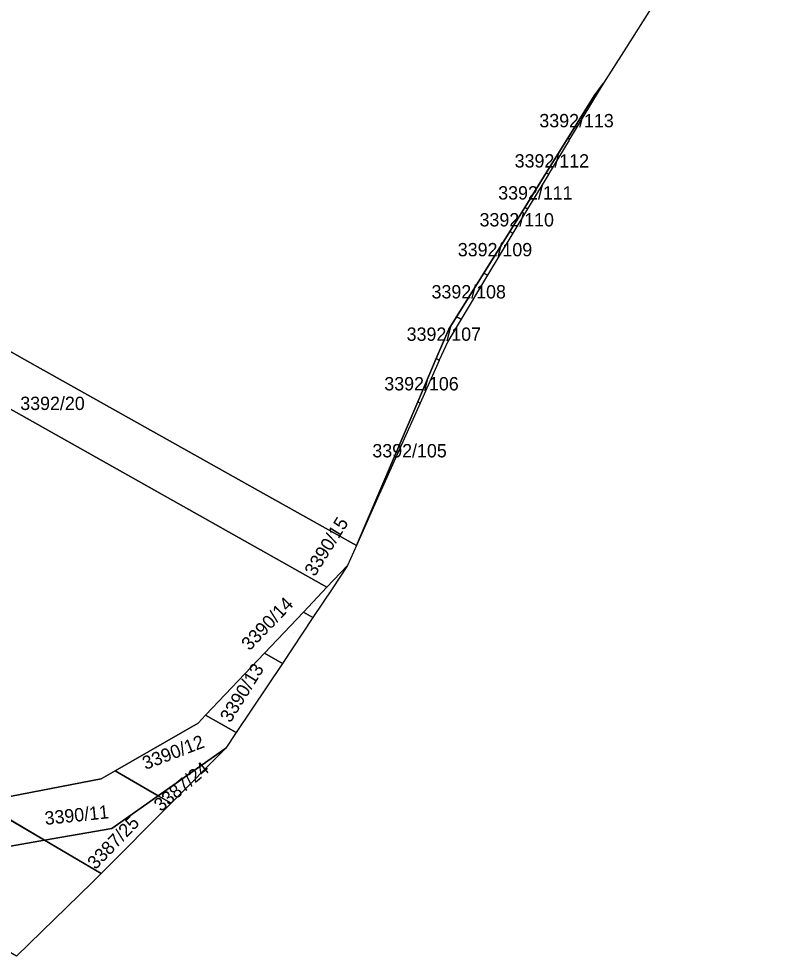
# Model space of a CAD drawing. Extents: x -262715 to -259381, y -1237238 to -1231182.
# Drawn here: x -261530.6 to -261416.5, y -1236783.3 to -1236642.6 of the extents above; entities that cross this region are included whole.
import ezdxf

# ---------------------------------------------------------------- set-up
doc = ezdxf.new("R2010")
doc.units = 0
for name, color, linetype in [('body_kn', 7, 'Continuous'), ('katuz_linie', 7, 'Continuous'), ('kladpar_druhypozemkov', 7, 'Continuous'), ('kladpar_hranice', 7, 'Continuous'), ('kladpar_parcelnecisla', 7, 'Continuous'), ('kladpar_plochy', 7, 'Continuous'), ('kladpar_sipky', 7, 'Continuous'), ('zuob_linie', 7, 'Continuous'), ('zuob_plochy', 7, 'Continuous')]:
    doc.layers.add(name, color=color, linetype=linetype)

msp = doc.modelspace()

# ---------------------------------------------------------------- linework, layer by layer
at = {"layer": 'body_kn'}
for p, q in [((-261439.9, -1236647.54), (-261439.9, -1236647.54)), ((-261442.9, -1236652.28), (-261442.9, -1236652.28)), ((-261444.29, -1236654.17), (-261444.29, -1236654.17)), ((-261443.68, -1236653.57), (-261443.68, -1236653.57)), ((-261448.25, -1236660.53), (-261448.25, -1236660.53)), ((-261448.25, -1236660.53), (-261448.25, -1236660.53)), ((-261448.03, -1236660.79), (-261448.03, -1236660.79)), ((-261447.97, -1236660.68), (-261447.97, -1236660.68)), ((-261447.97, -1236660.68), (-261447.97, -1236660.68)), ((-261451.48, -1236665.72), (-261451.48, -1236665.72)), ((-261451.48, -1236665.72), (-261451.48, -1236665.72)), ((-261451.15, -1236665.97), (-261451.15, -1236665.97)), ((-261451.12, -1236665.91), (-261451.12, -1236665.91)), ((-261451.12, -1236665.91), (-261451.12, -1236665.91)), ((-261454.71, -1236670.9), (-261454.71, -1236670.9)), ((-261454.71, -1236670.9), (-261454.71, -1236670.9)), ((-261454.27, -1236671.14), (-261454.27, -1236671.14)), ((-261454.27, -1236671.14), (-261454.27, -1236671.14)), ((-261456.96, -1236674.52), (-261456.96, -1236674.52)), ((-261456.96, -1236674.52), (-261456.96, -1236674.52)), ((-261456.47, -1236674.79), (-261456.47, -1236674.79)), ((-261456.47, -1236674.79), (-261456.47, -1236674.79)), ((-261460.85, -1236680.77), (-261460.85, -1236680.77)), ((-261460.85, -1236680.77), (-261460.85, -1236680.77)), ((-261460.27, -1236681.09), (-261460.27, -1236681.09)), ((-261460.27, -1236681.09), (-261460.27, -1236681.09)), ((-261464.93, -1236687.32), (-261464.93, -1236687.32)), ((-261464.93, -1236687.32), (-261464.93, -1236687.32)), ((-261464.25, -1236687.69), (-261464.25, -1236687.69)), ((-261464.25, -1236687.69), (-261464.25, -1236687.69)), ((-261466.08, -1236689.17), (-261466.08, -1236689.17)), ((-261466.25, -1236691.01), (-261466.25, -1236691.01)), ((-261467.97, -1236693.59), (-261467.97, -1236693.59)), ((-261467.97, -1236693.59), (-261467.97, -1236693.59)), ((-261467.52, -1236693.86), (-261467.52, -1236693.86)), ((-261467.51, -1236693.84), (-261467.51, -1236693.84)), ((-261467.51, -1236693.84), (-261467.51, -1236693.84)), ((-261528.1, -1236694.63), (-261528.1, -1236694.63)), ((-261470.74, -1236700.09), (-261470.74, -1236700.09)), ((-261470.74, -1236700.09), (-261470.74, -1236700.09)), ((-261470.4, -1236700.28), (-261470.4, -1236700.28)), ((-261470.4, -1236700.28), (-261470.4, -1236700.28)), ((-261515.83, -1236710.16), (-261515.83, -1236710.16)), ((-261495.14, -1236713.11), (-261495.14, -1236713.11)), ((-261476.47, -1236713.87), (-261476.47, -1236713.87)), ((-261476.57, -1236714.09), (-261476.57, -1236714.09)), ((-261479.94, -1236721.62), (-261479.94, -1236721.62)), ((-261479.94, -1236721.62), (-261479.94, -1236721.62)), ((-261481.29, -1236724.65), (-261481.29, -1236724.65)), ((-261484.37, -1236727.9), (-261484.37, -1236727.9)), ((-261484.37, -1236727.9), (-261484.37, -1236727.9)), ((-261483.6, -1236728.13), (-261483.6, -1236728.13)), ((-261487.9, -1236731.62), (-261487.9, -1236731.62)), ((-261487.9, -1236731.62), (-261487.9, -1236731.62)), ((-261486.46, -1236732.42), (-261486.46, -1236732.42)), ((-261486.46, -1236732.42), (-261486.46, -1236732.42)), ((-261493.75, -1236737.79), (-261493.75, -1236737.79)), ((-261493.75, -1236737.79), (-261493.75, -1236737.79)), ((-261491.05, -1236739.32), (-261491.05, -1236739.32)), ((-261491.05, -1236739.32), (-261491.05, -1236739.32)), ((-261502.57, -1236747.11), (-261502.57, -1236747.11)), ((-261502.57, -1236747.11), (-261502.57, -1236747.11)), ((-261503.69, -1236748.29), (-261503.69, -1236748.29)), ((-261497.96, -1236749.7), (-261497.96, -1236749.7)), ((-261497.96, -1236749.7), (-261497.96, -1236749.7)), ((-261499.52, -1236752.05), (-261499.52, -1236752.05)), ((-261516.11, -1236755.43), (-261516.11, -1236755.43)), ((-261516.11, -1236755.43), (-261516.11, -1236755.43)), ((-261518.22, -1236756.65), (-261518.22, -1236756.65)), ((-261509.65, -1236759.19), (-261509.65, -1236759.19)), ((-261509.65, -1236759.19), (-261509.65, -1236759.19)), ((-261507.73, -1236760.3), (-261507.73, -1236760.3)), ((-261507.73, -1236760.3), (-261507.73, -1236760.3)), ((-261516.6, -1236764.09), (-261516.6, -1236764.09)), ((-261526.69, -1236765.86), (-261526.69, -1236765.86)), ((-261526.69, -1236765.86), (-261526.69, -1236765.86)), ((-261518.23, -1236770.84), (-261518.23, -1236770.84)), ((-261518.23, -1236770.84), (-261518.23, -1236770.84)), ((-261519.57, -1236772.19), (-261519.57, -1236772.19))]:
    msp.add_line(p, q, dxfattribs=at)
at = {"layer": 'katuz_linie'}
msp.add_lwpolyline([(-261423.28, -1236621.31), (-261439.9, -1236647.54), (-261442.9, -1236652.28), (-261443.68, -1236653.57), (-261447.97, -1236660.68), (-261448.03, -1236660.79), (-261451.12, -1236665.91), (-261451.15, -1236665.97), (-261454.27, -1236671.14), (-261456.47, -1236674.79), (-261460.27, -1236681.09), (-261464.25, -1236687.69), (-261466.25, -1236691.01), (-261467.51, -1236693.84), (-261467.52, -1236693.86), (-261470.4, -1236700.28), (-261476.47, -1236713.87), (-261476.57, -1236714.09), (-261479.94, -1236721.62), (-261481.29, -1236724.65), (-261483.6, -1236728.13), (-261486.46, -1236732.42), (-261491.05, -1236739.32), (-261497.96, -1236749.7), (-261499.52, -1236752.05), (-261507.73, -1236760.3), (-261518.23, -1236770.84), (-261519.57, -1236772.19), (-261530.9, -1236783.26)], dxfattribs=at)
at = {"layer": 'kladpar_druhypozemkov'}
for p, q in [((-261446.4, -1236657.83), (-261446.4, -1236657.83)), ((-261450.05, -1236663.73), (-261450.05, -1236663.73)), ((-261452.82, -1236668.35), (-261452.82, -1236668.35)), ((-261455.31, -1236672.41), (-261455.31, -1236672.41)), ((-261457.99, -1236676.77), (-261457.99, -1236676.77)), ((-261461.79, -1236683.11), (-261461.79, -1236683.11)), ((-261465.48, -1236688.95), (-261465.48, -1236688.95)), ((-261469.01, -1236696.61), (-261469.01, -1236696.61)), ((-261525.16, -1236699.5), (-261525.16, -1236699.5)), ((-261471.8, -1236703.11), (-261471.8, -1236703.11)), ((-261486.85, -1236731.4), (-261486.85, -1236731.4)), ((-261491.01, -1236737.59), (-261491.01, -1236737.59)), ((-261500.27, -1236747.1), (-261500.27, -1236747.1)), ((-261505.42, -1236751.62), (-261505.42, -1236751.62)), ((-261507.92, -1236758.51), (-261507.92, -1236758.51)), ((-261521.72, -1236761.24), (-261521.72, -1236761.24)), ((-261519.87, -1236767.42), (-261519.87, -1236767.42))]:
    msp.add_line(p, q, dxfattribs=at)
at = {"layer": 'kladpar_hranice'}
for p, q in [((-261451.48, -1236665.72), (-261448.25, -1236660.53)), ((-261448.25, -1236660.53), (-261447.97, -1236660.68)), ((-261447.97, -1236660.68), (-261448.25, -1236660.53)), ((-261454.71, -1236670.9), (-261451.48, -1236665.72)), ((-261451.12, -1236665.91), (-261451.48, -1236665.72)), ((-261451.48, -1236665.72), (-261451.12, -1236665.91)), ((-261456.96, -1236674.52), (-261454.71, -1236670.9)), ((-261454.27, -1236671.14), (-261456.47, -1236674.79)), ((-261454.27, -1236671.14), (-261454.71, -1236670.9)), ((-261454.71, -1236670.9), (-261454.27, -1236671.14)), ((-261460.85, -1236680.77), (-261456.96, -1236674.52)), ((-261456.96, -1236674.52), (-261456.47, -1236674.79)), ((-261456.47, -1236674.79), (-261456.96, -1236674.52)), ((-261456.47, -1236674.79), (-261460.27, -1236681.09)), ((-261464.93, -1236687.32), (-261460.85, -1236680.77)), ((-261460.27, -1236681.09), (-261464.25, -1236687.69)), ((-261460.85, -1236680.77), (-261460.27, -1236681.09)), ((-261460.27, -1236681.09), (-261460.85, -1236680.77)), ((-261464.93, -1236687.32), (-261464.25, -1236687.69)), ((-261464.25, -1236687.69), (-261464.93, -1236687.32)), ((-261470.74, -1236700.09), (-261467.97, -1236693.59)), ((-261467.97, -1236693.59), (-261467.51, -1236693.84)), ((-261467.51, -1236693.84), (-261467.97, -1236693.59)), ((-261479.94, -1236721.62), (-261470.74, -1236700.09)), ((-261470.74, -1236700.09), (-261470.4, -1236700.28)), ((-261470.4, -1236700.28), (-261470.74, -1236700.09)), ((-261493.75, -1236737.79), (-261487.9, -1236731.62)), ((-261486.46, -1236732.42), (-261487.9, -1236731.62)), ((-261487.9, -1236731.62), (-261486.46, -1236732.42)), ((-261486.46, -1236732.42), (-261491.05, -1236739.32)), ((-261502.57, -1236747.11), (-261493.75, -1236737.79)), ((-261491.05, -1236739.32), (-261493.75, -1236737.79)), ((-261493.75, -1236737.79), (-261491.05, -1236739.32)), ((-261491.05, -1236739.32), (-261497.96, -1236749.7)), ((-261502.57, -1236747.11), (-261497.96, -1236749.7)), ((-261497.96, -1236749.7), (-261502.57, -1236747.11)), ((-261509.65, -1236759.19), (-261516.11, -1236755.43)), ((-261516.11, -1236755.43), (-261509.65, -1236759.19)), ((-261526.69, -1236765.86), (-261536.36, -1236760.16)), ((-261536.36, -1236760.16), (-261526.69, -1236765.86)), ((-261507.73, -1236760.3), (-261518.23, -1236770.84)), ((-261507.73, -1236760.3), (-261509.65, -1236759.19)), ((-261509.65, -1236759.19), (-261507.73, -1236760.3)), ((-261518.23, -1236770.84), (-261526.69, -1236765.86)), ((-261526.69, -1236765.86), (-261518.23, -1236770.84))]:
    msp.add_line(p, q, dxfattribs=at)
for points in [[(-261581.96, -1236557.12), (-261580.91, -1236548.23), (-261580.99, -1236545.13), (-261581.51, -1236525.81), (-261553.39, -1236545.48), (-261539.01, -1236515.59), (-261475.98, -1236549.48), (-261416.54, -1236607.89), (-261423.28, -1236621.31), (-261439.9, -1236647.54), (-261442.9, -1236652.28), (-261444.29, -1236654.17), (-261448.25, -1236660.53), (-261451.48, -1236665.72), (-261454.71, -1236670.9), (-261456.96, -1236674.52)], [(-261448.25, -1236660.53), (-261444.29, -1236654.17), (-261442.9, -1236652.28), (-261443.68, -1236653.57), (-261447.97, -1236660.68)], [(-261479.94, -1236721.62), (-261481.29, -1236724.65), (-261484.37, -1236727.9), (-261515.83, -1236710.16), (-261530.91, -1236701.65), (-261570.28, -1236679.67), (-261587.66, -1236669.96), (-261587.44, -1236661.56), (-261562.16, -1236675.49), (-261528.1, -1236694.63), (-261495.14, -1236713.11), (-261479.94, -1236721.62)], [(-261447.97, -1236660.68), (-261448.03, -1236660.79), (-261451.12, -1236665.91)], [(-261451.12, -1236665.91), (-261451.15, -1236665.97), (-261454.27, -1236671.14)], [(-261588.03, -1236684.42), (-261587.66, -1236669.96), (-261570.28, -1236679.67), (-261530.91, -1236701.65), (-261515.83, -1236710.16), (-261484.37, -1236727.9)], [(-261456.96, -1236674.52), (-261460.85, -1236680.77), (-261464.93, -1236687.32), (-261466.08, -1236689.17), (-261467.97, -1236693.59), (-261470.74, -1236700.09), (-261479.94, -1236721.62), (-261495.14, -1236713.11), (-261528.1, -1236694.63), (-261562.16, -1236675.49)], [(-261467.97, -1236693.59), (-261466.08, -1236689.17), (-261464.93, -1236687.32)], [(-261464.25, -1236687.69), (-261466.25, -1236691.01), (-261467.51, -1236693.84)], [(-261467.51, -1236693.84), (-261467.52, -1236693.86), (-261470.4, -1236700.28)], [(-261484.37, -1236727.9), (-261487.9, -1236731.62), (-261493.75, -1236737.79), (-261502.57, -1236747.11), (-261503.69, -1236748.29), (-261516.11, -1236755.43), (-261518.22, -1236756.65), (-261536.36, -1236760.16), (-261537.81, -1236760.44), (-261554.67, -1236756.97), (-261574.56, -1236742.18), (-261578.19, -1236735.52), (-261585.14, -1236722.79), (-261586.26, -1236714.69), (-261587.48, -1236705.78), (-261587.78, -1236703.62), (-261587.85, -1236699.27)], [(-261470.4, -1236700.28), (-261476.47, -1236713.87), (-261476.57, -1236714.09), (-261479.94, -1236721.62)], [(-261487.9, -1236731.62), (-261484.37, -1236727.9), (-261481.29, -1236724.65), (-261483.6, -1236728.13), (-261486.46, -1236732.42)], [(-261526.69, -1236765.86), (-261538.34, -1236767.9), (-261558.51, -1236763.51), (-261571.43, -1236755.44), (-261580.74, -1236746.42), (-261585.18, -1236739.92), (-261590, -1236730.13), (-261585.13, -1236751.39)], [(-261585.13, -1236751.39), (-261590, -1236730.13), (-261585.18, -1236739.92), (-261580.74, -1236746.42), (-261571.43, -1236755.44), (-261558.51, -1236763.51), (-261538.34, -1236767.9), (-261526.69, -1236765.86)], [(-261516.11, -1236755.43), (-261503.69, -1236748.29), (-261502.57, -1236747.11)], [(-261497.96, -1236749.7), (-261499.52, -1236752.05), (-261509.65, -1236759.19)], [(-261509.65, -1236759.19), (-261499.52, -1236752.05), (-261507.73, -1236760.3)], [(-261536.36, -1236760.16), (-261518.22, -1236756.65), (-261516.11, -1236755.43)], [(-261509.65, -1236759.19), (-261516.6, -1236764.09), (-261526.69, -1236765.86)], [(-261526.69, -1236765.86), (-261516.6, -1236764.09), (-261509.65, -1236759.19)], [(-261518.23, -1236770.84), (-261519.57, -1236772.19), (-261530.9, -1236783.26)]]:
    msp.add_lwpolyline(points, dxfattribs=at)
at = {"layer": 'kladpar_plochy'}
msp.add_lwpolyline([(-261423.28, -1236621.31), (-261439.9, -1236647.54), (-261442.9, -1236652.28), (-261444.29, -1236654.17), (-261448.25, -1236660.53), (-261451.48, -1236665.72), (-261454.71, -1236670.9), (-261456.96, -1236674.52), (-261460.85, -1236680.77), (-261464.93, -1236687.32), (-261466.08, -1236689.17), (-261467.97, -1236693.59), (-261470.74, -1236700.09), (-261479.94, -1236721.62), (-261495.14, -1236713.11), (-261528.1, -1236694.63), (-261562.16, -1236675.49), (-261558.33, -1236668.58), (-261587.21, -1236652.61), (-261586.6, -1236629.3)], dxfattribs=at)
for points in [[(-261448.25, -1236660.53), (-261444.29, -1236654.17), (-261442.9, -1236652.28), (-261443.68, -1236653.57), (-261447.97, -1236660.68)], [(-261451.48, -1236665.72), (-261448.25, -1236660.53), (-261447.97, -1236660.68), (-261448.03, -1236660.79), (-261451.12, -1236665.91)], [(-261479.94, -1236721.62), (-261481.29, -1236724.65), (-261484.37, -1236727.9), (-261515.83, -1236710.16), (-261530.91, -1236701.65), (-261570.28, -1236679.67), (-261587.66, -1236669.96), (-261587.44, -1236661.56), (-261562.16, -1236675.49), (-261528.1, -1236694.63), (-261495.14, -1236713.11)], [(-261454.27, -1236671.14), (-261454.71, -1236670.9), (-261451.48, -1236665.72), (-261451.12, -1236665.91), (-261451.15, -1236665.97)], [(-261484.37, -1236727.9), (-261487.9, -1236731.62), (-261493.75, -1236737.79), (-261502.57, -1236747.11), (-261503.69, -1236748.29), (-261516.11, -1236755.43), (-261518.22, -1236756.65), (-261536.36, -1236760.16), (-261537.81, -1236760.44), (-261554.67, -1236756.97), (-261574.56, -1236742.18), (-261578.19, -1236735.52), (-261585.14, -1236722.79), (-261586.26, -1236714.69), (-261587.48, -1236705.78), (-261587.78, -1236703.62), (-261587.85, -1236699.27), (-261578.96, -1236704.26), (-261576.72, -1236690.83), (-261588.03, -1236684.42), (-261587.66, -1236669.96), (-261570.28, -1236679.67), (-261530.91, -1236701.65), (-261515.83, -1236710.16)], [(-261454.71, -1236670.9), (-261454.27, -1236671.14), (-261456.47, -1236674.79), (-261456.96, -1236674.52)], [(-261460.85, -1236680.77), (-261456.96, -1236674.52), (-261456.47, -1236674.79), (-261460.27, -1236681.09)], [(-261464.93, -1236687.32), (-261460.85, -1236680.77), (-261460.27, -1236681.09), (-261464.25, -1236687.69)], [(-261467.97, -1236693.59), (-261466.08, -1236689.17), (-261464.93, -1236687.32), (-261464.25, -1236687.69), (-261466.25, -1236691.01), (-261467.51, -1236693.84)], [(-261470.74, -1236700.09), (-261467.97, -1236693.59), (-261467.51, -1236693.84), (-261467.52, -1236693.86), (-261470.4, -1236700.28)], [(-261479.94, -1236721.62), (-261470.74, -1236700.09), (-261470.4, -1236700.28), (-261476.47, -1236713.87), (-261476.57, -1236714.09)], [(-261536.36, -1236760.16), (-261526.69, -1236765.86), (-261538.34, -1236767.9), (-261558.51, -1236763.51), (-261571.43, -1236755.44), (-261580.74, -1236746.42), (-261585.18, -1236739.92), (-261590, -1236730.13), (-261585.13, -1236751.39), (-261595.45, -1236745.32), (-261597.63, -1236735.85), (-261599.71, -1236726.01), (-261600.23, -1236722.54), (-261578.19, -1236735.52), (-261574.56, -1236742.18), (-261554.67, -1236756.97), (-261537.81, -1236760.44)], [(-261487.9, -1236731.62), (-261484.37, -1236727.9), (-261481.29, -1236724.65), (-261483.6, -1236728.13), (-261486.46, -1236732.42)], [(-261526.69, -1236765.86), (-261518.23, -1236770.84), (-261519.57, -1236772.19), (-261530.9, -1236783.26), (-261585.13, -1236751.39), (-261590, -1236730.13), (-261585.18, -1236739.92), (-261580.74, -1236746.42), (-261571.43, -1236755.44), (-261558.51, -1236763.51), (-261538.34, -1236767.9)], [(-261487.9, -1236731.62), (-261486.46, -1236732.42), (-261491.05, -1236739.32), (-261493.75, -1236737.79)], [(-261493.75, -1236737.79), (-261491.05, -1236739.32), (-261497.96, -1236749.7), (-261502.57, -1236747.11)], [(-261502.57, -1236747.11), (-261497.96, -1236749.7), (-261499.52, -1236752.05), (-261509.65, -1236759.19), (-261516.11, -1236755.43), (-261503.69, -1236748.29)], [(-261509.65, -1236759.19), (-261499.52, -1236752.05), (-261507.73, -1236760.3)], [(-261516.11, -1236755.43), (-261509.65, -1236759.19), (-261516.6, -1236764.09), (-261526.69, -1236765.86), (-261536.36, -1236760.16), (-261518.22, -1236756.65)], [(-261509.65, -1236759.19), (-261507.73, -1236760.3), (-261518.23, -1236770.84), (-261526.69, -1236765.86), (-261516.6, -1236764.09)]]:
    msp.add_lwpolyline(points, close=True, dxfattribs=at)
at = {"layer": 'kladpar_sipky'}
for p, q in [((-261486.14, -1236730.28), (-261486.14, -1236730.28)), ((-261489.42, -1236734.72), (-261489.42, -1236734.72))]:
    msp.add_line(p, q, dxfattribs=at)
at = {"layer": 'zuob_linie'}
msp.add_lwpolyline([(-261423.28, -1236621.31), (-261439.9, -1236647.54), (-261442.9, -1236652.28), (-261443.68, -1236653.57), (-261447.97, -1236660.68), (-261448.03, -1236660.79), (-261451.12, -1236665.91), (-261451.15, -1236665.97), (-261454.27, -1236671.14), (-261456.47, -1236674.79), (-261460.27, -1236681.09), (-261464.25, -1236687.69), (-261466.25, -1236691.01), (-261467.51, -1236693.84), (-261467.52, -1236693.86), (-261470.4, -1236700.28), (-261476.47, -1236713.87), (-261476.57, -1236714.09), (-261479.94, -1236721.62), (-261481.29, -1236724.65), (-261483.6, -1236728.13), (-261486.46, -1236732.42), (-261491.05, -1236739.32), (-261497.96, -1236749.7), (-261499.52, -1236752.05), (-261507.73, -1236760.3), (-261518.23, -1236770.84), (-261519.57, -1236772.19), (-261530.9, -1236783.26)], dxfattribs=at)
at = {"layer": 'zuob_plochy'}
msp.add_lwpolyline([(-261423.28, -1236621.31), (-261439.9, -1236647.54), (-261442.9, -1236652.28), (-261443.68, -1236653.57), (-261447.97, -1236660.68), (-261448.03, -1236660.79), (-261451.12, -1236665.91), (-261451.15, -1236665.97), (-261454.27, -1236671.14), (-261456.47, -1236674.79), (-261460.27, -1236681.09), (-261464.25, -1236687.69), (-261466.25, -1236691.01), (-261467.51, -1236693.84), (-261467.52, -1236693.86), (-261470.4, -1236700.28), (-261476.47, -1236713.87), (-261476.57, -1236714.09), (-261479.94, -1236721.62), (-261481.29, -1236724.65), (-261483.6, -1236728.13), (-261486.46, -1236732.42), (-261491.05, -1236739.32), (-261497.96, -1236749.7), (-261499.52, -1236752.05), (-261507.73, -1236760.3), (-261518.23, -1236770.84), (-261519.57, -1236772.19), (-261530.9, -1236783.26)], dxfattribs=at)

# ---------------------------------------------------------------- texts
at = {"layer": 'kladpar_parcelnecisla'}
for s, p in [('3392/113', (-261452.51, -1236658.88)), ('3392/112', (-261456.21, -1236664.92)), ('3392/111', (-261458.68, -1236669.72)), ('3392/110', (-261461.48, -1236673.76)), ('3392/109', (-261464.74, -1236678.24)), ('3392/108', (-261468.68, -1236684.56)), ('3392/107', (-261472.41, -1236690.92)), ('3392/106', (-261475.76, -1236698.36)), ('3392/20', (-261530.35, -1236701.3)), ('3392/105', (-261477.55, -1236708.41))]:
    msp.add_text(s, height=2, dxfattribs=at).set_placement(p)
for s, rotation, p in [('3390/15', 58, (-261486.18, -1236726.4)), ('3390/14', 46, (-261495.97, -1236737.52)), ('3390/13', 58, (-261498.85, -1236748.34)), ('3390/12', 21, (-261511.58, -1236755.32)), ('3387/24', 40, (-261509.26, -1236761.66)), ('3390/11', 6, (-261526.59, -1236763.56)), ('3387/25', 46, (-261519.06, -1236770.35))]:
    msp.add_text(s, height=2, rotation=rotation, dxfattribs=at).set_placement(p)

doc.saveas('drawing.dxf')
